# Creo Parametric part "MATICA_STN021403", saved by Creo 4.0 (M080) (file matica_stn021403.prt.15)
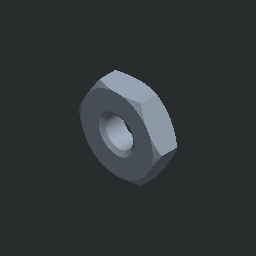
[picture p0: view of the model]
Units: Custom; MM, KILOGRAM, SECS
Materials in the file: OCEL, OCEL_N

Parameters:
  PTC_MATERIAL_NAME = "OCEL"
  NAZOV = "MATICA_STN021403"
  NORMA = "STN 02 1403"

Other parameters: HMOTNOST, HUSTOTA, D12, D19

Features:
  1. datum plane "DTM1"
  2. cut
  3. cut
  4. datum plane "DTM2"
  5. datum plane "DTM3"

Other named items: THRU

Layers: 1, 2, 3, 4, 5, 6, 7, 8, 9, 10, 11, 12, 13, 14, 15, 16, 17, 18, 19, 20, 21, 22, 23, 24, 25, 26, 27, 28, 29, 30, 31, 32

Family table entries: GENERIC, MATICA_M1_6, MATICA_STN021403, value(d_val), value(i_val), MATICA_M2, MATICA_STN021403, MATICA_M2_5, MATICA_STN021403, MATICA_M3, MATICA_STN021403, MATICA_M4, MATICA_STN021403, MATICA_M5, MATICA_STN021403, 2/ , MATICA_M6, MATICA_STN021403, 2/$, MATICA_M8, MATICA_STN021403, !/ , 2/$, MATICA_M8X1, MATICA_STN021403, !/ , 2/$, MATICA_M10, MATICA_STN021403, !/$, 2/0, MATICA_M10X1_25, MATICA_STN021403, !/$, 2/0, MATICA_M12, MATICA_STN021403, !/(, 2/2, MATICA_M12X1_25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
